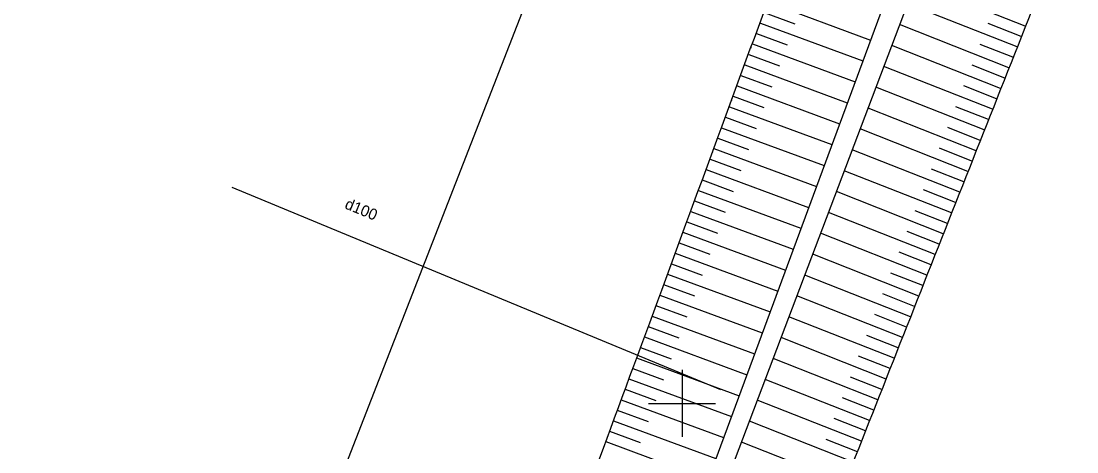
# Model space of a CAD drawing. Extents: x 616607 to 617499, y 408385 to 409695.
# Drawn here: x 617070.38 to 617117.69, y 408797.83 to 408817.13 of the extents above; entities that cross this region are included whole.
import ezdxf

# ---------------------------------------------------------------- set-up
doc = ezdxf.new("R2010")
doc.units = 0
for name, color, linetype in [('DREN_VADP_####_####_#', 7, 'Continuous'), ('DREN_VADP_####_TKST_#', 7, 'Continuous'), ('GEOD_ELEM_####_####_#', 7, 'Continuous'), ('HIDG_GRAV_####_####_#', 7, 'Continuous'), ('RAMI_UZMR_####_####_#', 7, 'Continuous'), ('RELJ_NOGA_####_####_#', 7, 'Continuous')]:
    doc.layers.add(name, color=color, linetype=linetype)

# ---------------------------------------------------------------- blocks, each defined once
blk = doc.blocks.new('KRUSTS')
at = {"layer": 'GEOD_ELEM_####_####_#'}
for p, q in [((0, 1.5), (0, 0)), ((-1.5, 0), (0, 0)), ((0, 0), (0, -1.5)), ((0, 0), (1.5, 0))]:
    blk.add_line(p, q, dxfattribs=at)

msp = doc.modelspace()

# ---------------------------------------------------------------- linework, layer by layer
at = {"layer": 'DREN_VADP_####_####_#'}
msp.add_lwpolyline([(617101.736, 408800.602), (617079.845, 408809.673)], dxfattribs=at)
at = {"layer": 'HIDG_GRAV_####_####_#'}
msp.add_lwpolyline([(616957.708, 408604.801), (616964.717, 408618.582), (616997.814, 408672.816), (617082.506, 408751.106), (617088.497, 408760.889), (617116.937, 408835.934), (617137.451, 408884.548), (617152.78, 408924.733), (617163.79, 408955.542), (617160.997, 408956.152), (617115.742, 408836.043), (617088.001, 408760.943), (617081.506, 408751.106), (616997.147, 408673.705), (616963.717, 408618.582), (616956.708, 408604.801)], dxfattribs=at)
at = {"layer": 'RAMI_UZMR_####_####_#'}
msp.add_lwpolyline([(617191.828, 409115.62), (617145.545, 408952.8), (617072.809, 408766.141), (616965.332, 408652.076), (616939.432, 408594.661), (616924.839, 408592.467), (616706.433, 408526.081), (616666.426, 408467.691)], dxfattribs=at)
at = {"layer": 'RELJ_NOGA_####_####_#'}
for p, q in [((617115.378, 408816.906), (617110.461, 408818.846)), ((617103.857, 408817.985), (617108.444, 408816.284)), ((617115.011, 408815.976), (617110.107, 408817.911)), ((617103.683, 408817.516), (617105.059, 408817.006)), ((617103.453, 408816.895), (617103.453, 408816.895)), ((617103.509, 408817.047), (617108.098, 408815.347)), ((617114.644, 408815.046), (617109.752, 408816.975)), ((617115.194, 408816.441), (617113.721, 408817.022)), ((617103.279, 408816.426), (617103.28, 408816.426)), ((617103.335, 408816.578), (617104.712, 408816.068)), ((617103.105, 408815.957), (617103.106, 408815.957)), ((617103.162, 408816.109), (617107.751, 408814.409)), ((617114.277, 408814.116), (617109.398, 408816.04)), ((617114.827, 408815.511), (617113.358, 408816.091)), ((617102.932, 408815.488), (617102.933, 408815.488)), ((617102.988, 408815.641), (617104.365, 408815.131)), ((617102.758, 408815.019), (617102.758, 408815.019)), ((617102.815, 408815.172), (617107.405, 408813.473)), ((617113.91, 408813.185), (617109.043, 408815.105)), ((617114.46, 408814.581), (617112.995, 408815.159)), ((617102.585, 408814.55), (617102.586, 408814.55)), ((617102.641, 408814.703), (617104.018, 408814.193)), ((617102.411, 408814.082), (617102.411, 408814.081)), ((617102.467, 408814.234), (617107.059, 408812.536)), ((617113.543, 408812.255), (617108.689, 408814.17)), ((617114.093, 408813.651), (617112.632, 408814.227)), ((617102.238, 408813.613), (617102.239, 408813.612)), ((617102.294, 408813.765), (617103.672, 408813.255)), ((617102.064, 408813.144), (617102.065, 408813.143)), ((617102.121, 408813.296), (617106.712, 408811.598)), ((617113.176, 408811.325), (617108.335, 408813.235)), ((617113.727, 408812.72), (617112.268, 408813.295)), ((617101.891, 408812.675), (617101.892, 408812.674)), ((617101.947, 408812.827), (617103.325, 408812.317)), ((617101.718, 408812.206), (617101.718, 408812.206)), ((617101.774, 408812.358), (617106.366, 408810.661)), ((617112.809, 408810.395), (617107.98, 408812.3)), ((617113.36, 408811.79), (617111.905, 408812.364)), ((617101.544, 408811.737), (617101.545, 408811.736)), ((617101.601, 408811.889), (617102.978, 408811.38)), ((617101.371, 408811.268), (617101.371, 408811.267)), ((617101.427, 408811.42), (617106.02, 408809.723)), ((617112.442, 408809.465), (617107.626, 408811.365)), ((617112.993, 408810.86), (617111.542, 408811.432)), ((617101.198, 408810.799), (617101.199, 408810.798)), ((617101.254, 408810.951), (617102.632, 408810.442)), ((617101.025, 408810.33), (617101.025, 408810.329)), ((617101.081, 408810.482), (617105.674, 408808.786)), ((617112.075, 408808.534), (617107.272, 408810.429)), ((617112.626, 408809.93), (617111.179, 408810.5)), ((617100.851, 408809.86), (617100.852, 408809.86)), ((617100.908, 408810.013), (617102.286, 408809.504)), ((617100.678, 408809.391), (617100.679, 408809.391)), ((617100.735, 408809.544), (617105.327, 408807.848)), ((617111.708, 408807.604), (617106.917, 408809.494)), ((617112.259, 408808.999), (617110.816, 408809.569)), ((617100.505, 408808.922), (617100.506, 408808.922)), ((617100.561, 408809.075), (617101.939, 408808.566)), ((617100.332, 408808.453), (617100.332, 408808.453)), ((617100.388, 408808.606), (617104.981, 408806.91)), ((617111.341, 408806.674), (617106.563, 408808.559)), ((617111.892, 408808.069), (617110.453, 408808.637)), ((617100.159, 408807.984), (617100.16, 408807.984)), ((617100.215, 408808.137), (617101.593, 408807.628)), ((617111.525, 408807.139), (617110.089, 408807.705)), ((617099.986, 408807.515), (617099.986, 408807.515)), ((617100.042, 408807.667), (617104.634, 408805.972)), ((617110.974, 408805.744), (617106.208, 408807.623)), ((617099.813, 408807.046), (617099.813, 408807.046)), ((617099.869, 408807.198), (617101.247, 408806.69)), ((617111.158, 408806.209), (617109.726, 408806.773)), ((617099.639, 408806.577), (617099.64, 408806.577)), ((617099.696, 408806.729), (617104.288, 408805.035)), ((617110.607, 408804.813), (617105.854, 408806.688)), ((617099.466, 408806.108), (617099.467, 408806.108)), ((617099.523, 408806.26), (617100.9, 408805.752)), ((617110.791, 408805.278), (617109.363, 408805.842)), ((617099.293, 408805.639), (617099.294, 408805.639)), ((617099.35, 408805.791), (617103.942, 408804.097)), ((617110.241, 408803.883), (617105.499, 408805.752)), ((617099.12, 408805.17), (617099.121, 408805.169)), ((617099.176, 408805.322), (617100.554, 408804.814)), ((617110.424, 408804.348), (617109, 408804.91)), ((617098.947, 408804.701), (617098.947, 408804.701)), ((617099.003, 408804.853), (617103.595, 408803.159)), ((617109.874, 408802.953), (617105.145, 408804.817)), ((617098.774, 408804.232), (617098.775, 408804.231)), ((617098.83, 408804.384), (617100.208, 408803.876)), ((617110.057, 408803.418), (617108.637, 408803.978)), ((617098.484, 408803.446), (617099.862, 408802.937)), ((617098.601, 408803.762), (617098.601, 408803.762)), ((617098.657, 408803.915), (617103.249, 408802.221)), ((617109.507, 408802.022), (617104.79, 408803.882)), ((617098.311, 408802.977), (617102.902, 408801.283)), ((617098.428, 408803.293), (617098.429, 408803.293)), ((617109.69, 408802.488), (617108.274, 408803.046)), ((617098.138, 408802.507), (617099.515, 408801.999)), ((617098.255, 408802.824), (617098.255, 408802.824)), ((617109.14, 408801.092), (617104.435, 408802.946)), ((617097.965, 408802.038), (617102.555, 408800.344)), ((617098.082, 408802.355), (617098.083, 408802.355)), ((617109.324, 408801.557), (617107.91, 408802.114)), ((617097.792, 408801.569), (617099.169, 408801.061)), ((617097.909, 408801.886), (617097.909, 408801.886)), ((617108.774, 408800.162), (617104.081, 408802.011)), ((617097.619, 408801.1), (617102.209, 408799.406)), ((617097.736, 408801.417), (617097.737, 408801.417)), ((617108.957, 408800.627), (617107.547, 408801.182)), ((617097.446, 408800.631), (617098.823, 408800.123)), ((617097.563, 408800.948), (617097.563, 408800.948)), ((617108.407, 408799.231), (617103.727, 408801.075)), ((617097.272, 408800.162), (617101.862, 408798.468)), ((617097.389, 408800.479), (617097.39, 408800.479)), ((617108.041, 408798.301), (617103.372, 408800.139)), ((617108.591, 408799.696), (617107.185, 408800.25)), ((617097.099, 408799.693), (617098.476, 408799.185)), ((617097.216, 408800.01), (617097.217, 408800.01)), ((617096.926, 408799.224), (617101.516, 408797.53)), ((617097.043, 408799.541), (617097.044, 408799.54)), ((617107.675, 408797.37), (617103.017, 408799.204)), ((617108.224, 408798.766), (617106.822, 408799.319)), ((617096.753, 408798.755), (617098.13, 408798.247)), ((617096.87, 408799.072), (617096.87, 408799.072)), ((617096.58, 408798.286), (617101.169, 408796.592)), ((617096.697, 408798.603), (617096.698, 408798.602)), ((617107.308, 408796.44), (617102.663, 408798.267)), ((617107.858, 408797.836), (617106.459, 408798.386)), ((617096.524, 408798.133), (617096.524, 408798.133))]:
    msp.add_line(p, q, dxfattribs=at)
for points in [[(616952.11, 408607.531), (616956.151, 408614.166), (616960.13, 408620.838), (616964.128, 408627.499), (616969.357, 408636.209), (616974.533, 408644.951), (616979.755, 408653.666), (616982.367, 408658.027), (616985.018, 408662.364), (616987.709, 408666.677), (616989.056, 408668.838), (616990.438, 408670.976), (616991.835, 408673.105), (616992.534, 408674.172), (616993.243, 408675.231), (616993.95, 408676.293), (616994.657, 408677.356), (616995.377, 408678.409), (616996.104, 408679.46), (616998.164, 408682.436), (617000.493, 408685.215), (617003.037, 408687.806), (617005.59, 408690.406), (617008.236, 408692.879), (617011.016, 408695.214), (617013.812, 408697.562), (617016.632, 408699.88), (617019.423, 408702.233), (617020.817, 408703.408), (617022.221, 408704.57), (617023.595, 408705.77), (617024.962, 408706.965), (617026.3, 408708.194), (617027.642, 408709.417), (617031.797, 408713.202), (617035.92, 408717.024), (617040.083, 408720.8), (617044.243, 408724.572), (617048.471, 408728.267), (617052.642, 408732.025), (617056.824, 408735.794), (617060.981, 408739.59), (617065.093, 408743.436), (617067.159, 408745.369), (617069.191, 408747.335), (617071.208, 408749.318), (617072.22, 408750.314), (617073.221, 408751.32), (617074.226, 408752.322), (617075.234, 408753.328), (617076.23, 408754.338), (617077.212, 408755.375), (617081.698, 408760.112), (617084.989, 408765.985), (617087.243, 408772.093), (617089.541, 408778.321), (617091.528, 408784.634), (617093.829, 408790.846), (617099.646, 408806.547), (617105.384, 408822.279), (617111.331, 408837.932), (617116.967, 408852.766), (617122.795, 408867.526), (617128.465, 408882.346), (617134.52, 408898.17), (617140.109, 408914.165), (617146.15, 408930), (617147.203, 408932.762), (617148.413, 408935.46), (617149.608, 408938.162), (617150.805, 408940.87), (617152.218, 408943.437), (617153.491, 408946.151), (617155.134, 408949.654), (617156.252, 408953.338), (617157.386, 408956.937), (617157.388, 408956.942), (617157.376, 408956.956), (617157.382, 408956.955), (617158.587, 408956.687), (617159.792, 408956.42), (617160.997, 408956.152)], [(617163.79, 408955.542), (617165.45, 408955.194), (617167.11, 408954.846), (617168.77, 408954.498), (617168.913, 408954.468), (617169.034, 408954.324), (617169.074, 408954.183), (617169.128, 408953.99), (617169.08, 408953.773), (617169.007, 408953.587), (617168.835, 408953.148), (617168.665, 408952.708), (617168.483, 408952.272), (617167.485, 408949.894), (617166.495, 408947.512), (617165.486, 408945.138), (617164.477, 408942.762), (617163.444, 408940.395), (617162.435, 408938.019), (617160.416, 408933.265), (617158.392, 408928.513), (617156.542, 408923.692), (617150.713, 408908.507), (617144.931, 408893.305), (617139.111, 408878.118), (617136.201, 408870.523), (617133.294, 408862.928), (617130.378, 408855.336), (617127.463, 408847.744), (617124.504, 408840.168), (617121.547, 408832.592), (617116.624, 408819.98), (617111.621, 408807.399), (617106.663, 408794.801), (617101.918, 408782.741), (617097.386, 408770.604), (617092.68, 408758.522), (617091.748, 408756.128), (617090.638, 408753.8), (617089.099, 408751.701), (617087.891, 408750.055), (617086.512, 408748.607), (617085.075, 408747.191), (617082.094, 408744.254), (617079.138, 408741.303), (617076.078, 408738.453), (617073.02, 408735.605), (617069.97, 408732.751), (617066.861, 408729.96), (617060.644, 408724.38), (617054.349, 408718.89), (617048.124, 408713.32), (617041.902, 408707.753), (617035.717, 408702.149), (617029.576, 408696.491), (617026.506, 408693.662), (617023.563, 408690.704), (617020.596, 408687.763), (617017.626, 408684.818), (617014.683, 408681.855), (617011.931, 408678.697), (617008.517, 408674.776), (617005.359, 408670.661), (617002.288, 408666.476), (616999.318, 408662.428), (616996.36, 408658.374), (616993.424, 408654.302), (616990.492, 408650.235), (616987.575, 408646.161), (616984.691, 408642.059), (616983.288, 408640.063), (616981.951, 408638.02), (616980.703, 408635.922), (616979.453, 408633.819), (616978.237, 408631.7), (616977.033, 408629.572), (616975.83, 408627.444), (616974.65, 408625.305), (616973.452, 408623.174), (616972.259, 408621.052), (616970.984, 408618.974), (616969.729, 408616.893), (616969.613, 408616.701), (616969.41, 408616.592), (616969.29, 408616.383), (616968.995, 408615.872), (616968.948, 408615.291), (616969.02, 408614.761), (616969.09, 408614.251), (616969.19, 408613.683), (616969.493, 408613.251)]]:
    msp.add_open_spline(points, degree=3, dxfattribs=at)

# ---------------------------------------------------------------- block references
at = {"layer": 'GEOD_ELEM_####_####_#'}
msp.add_blockref('KRUSTS', (617100, 408800), dxfattribs=at)

# ---------------------------------------------------------------- texts
at = {"layer": 'DREN_VADP_####_TKST_#'}
msp.add_text('d100', height=0.5, rotation=337.4706, dxfattribs=at).set_placement((617084.847, 408808.753))

doc.saveas('drawing.dxf')
